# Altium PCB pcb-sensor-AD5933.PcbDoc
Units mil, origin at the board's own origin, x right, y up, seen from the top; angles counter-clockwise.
Board outline 2110 x 1945 mil, 2 copper layers (Top Layer, Bottom Layer); 28 components, 19 nets, 94 pads, 22 vias.
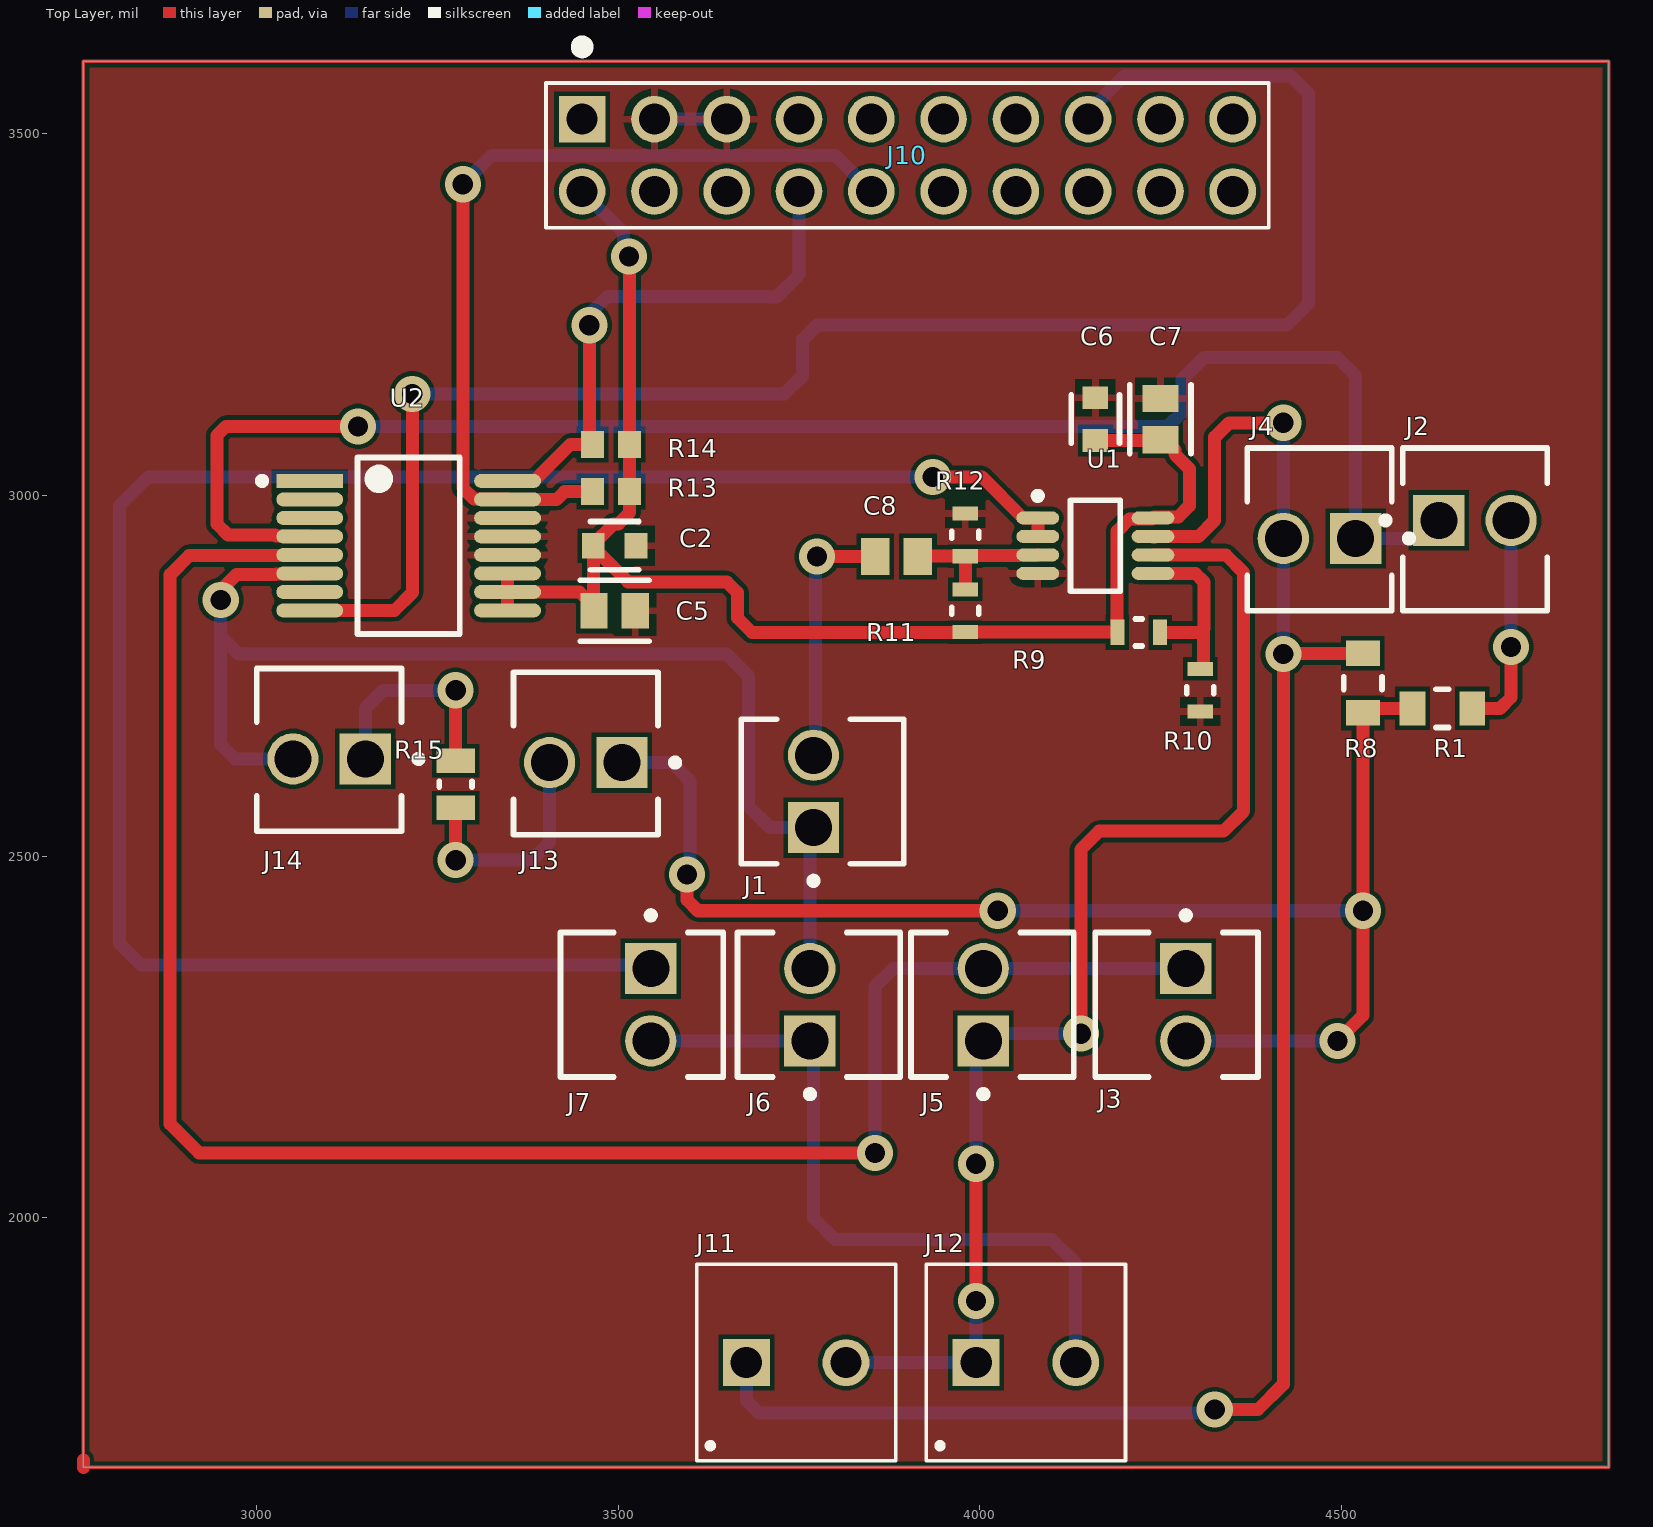
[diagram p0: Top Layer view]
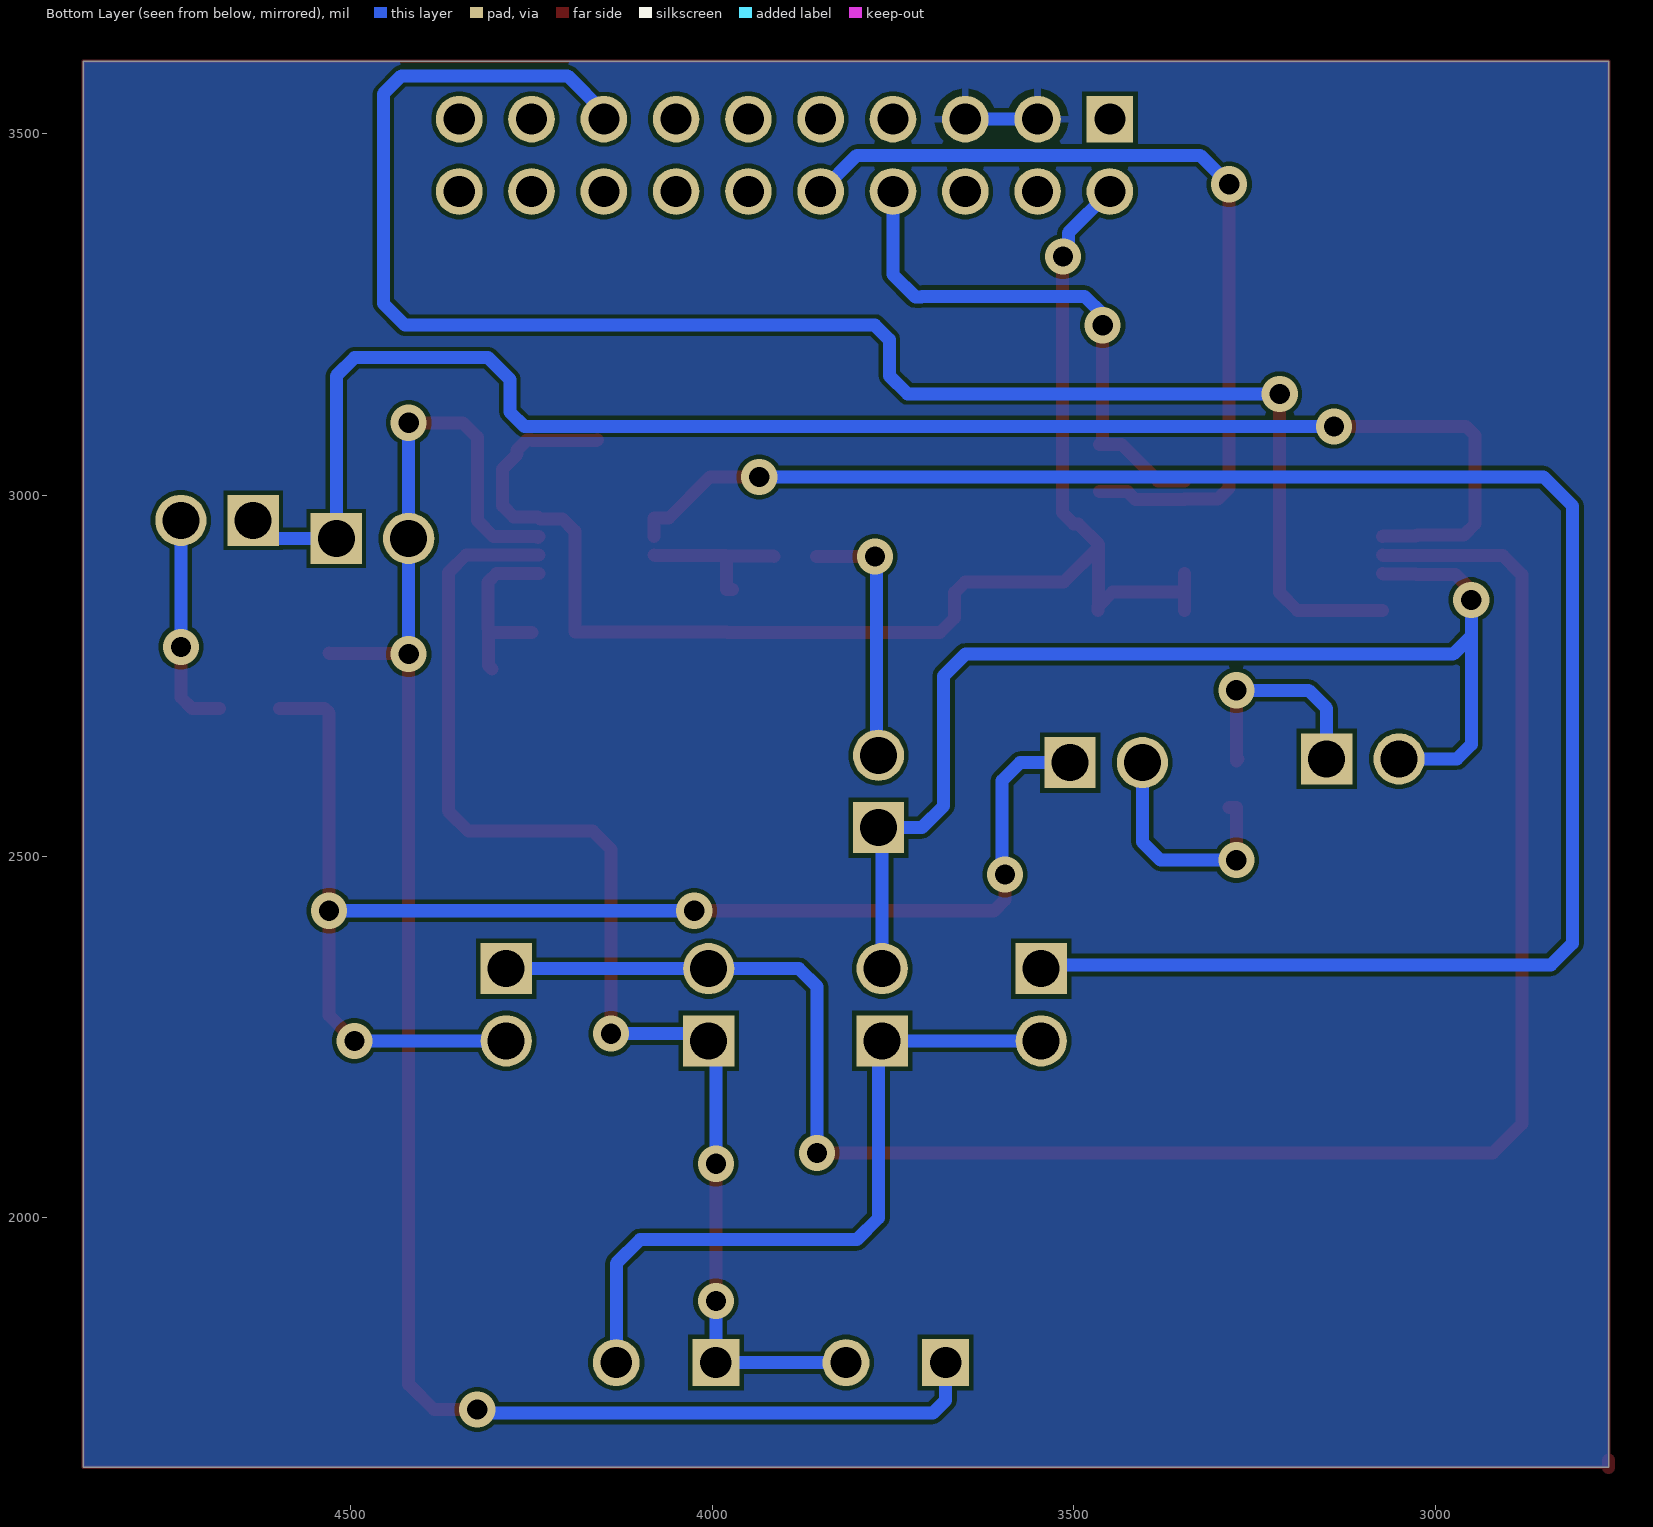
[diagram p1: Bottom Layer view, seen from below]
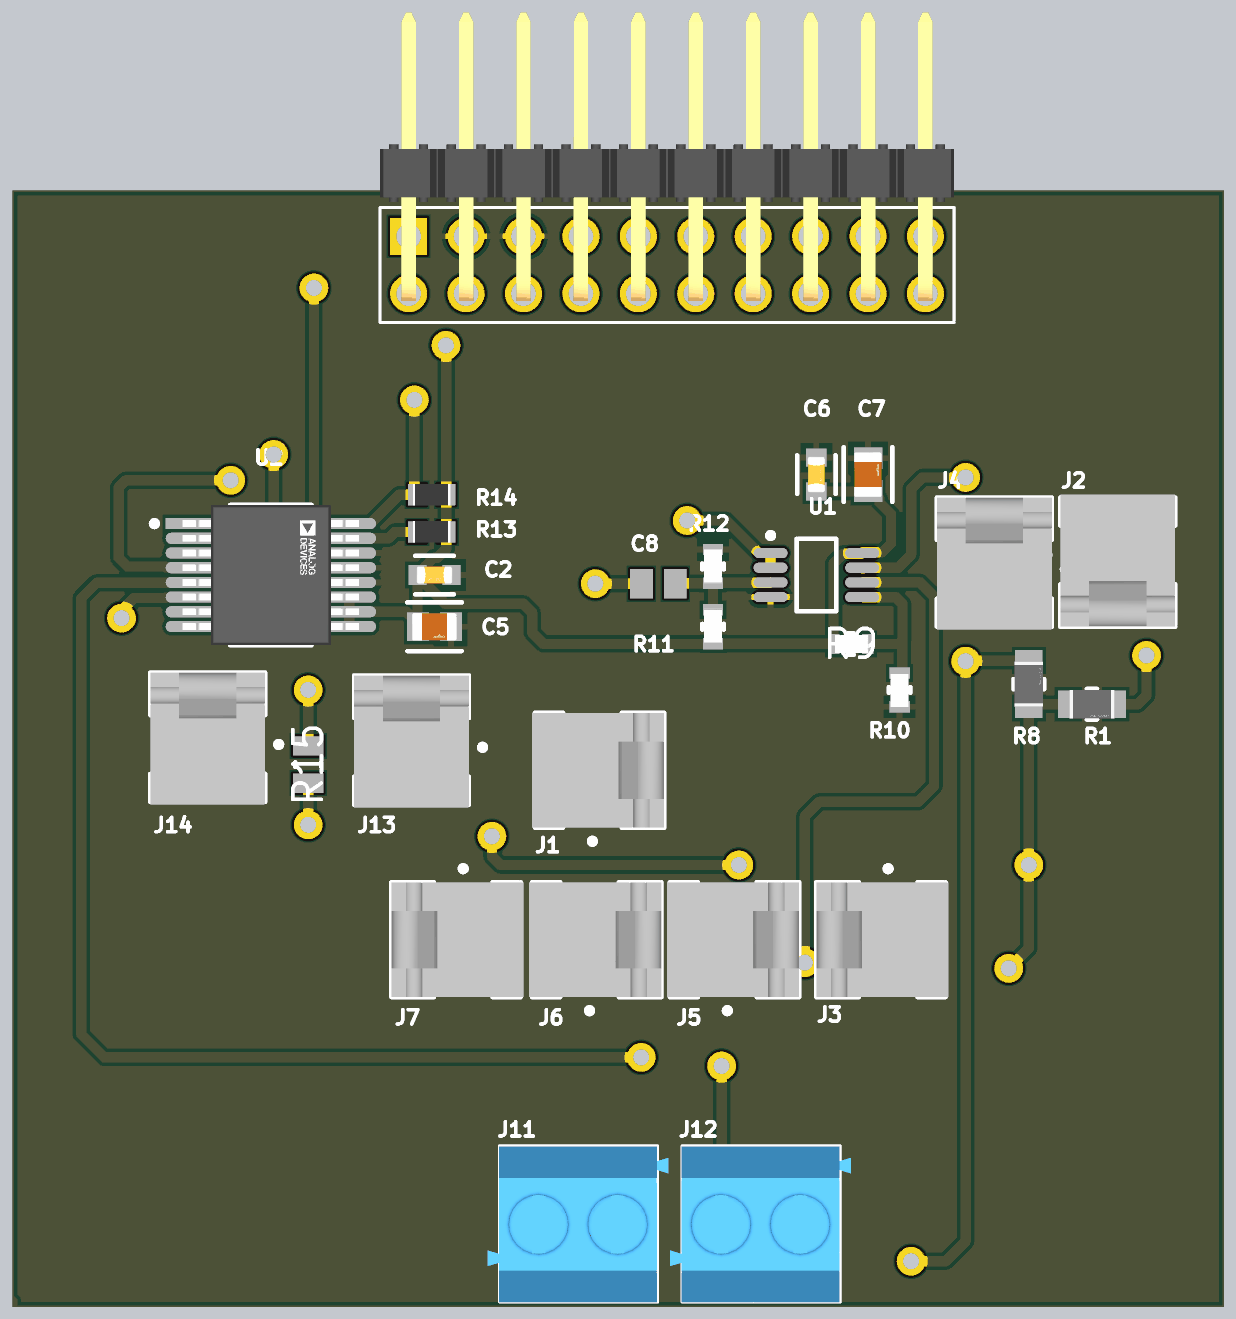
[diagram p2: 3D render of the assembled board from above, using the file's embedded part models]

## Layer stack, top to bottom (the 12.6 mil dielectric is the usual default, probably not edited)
Top Solder: solder mask 0.4, Solder Resist, Dk 3.5
Top Layer: signal copper 1.4
Dielectric 1: dielectric 12.6, FR-4, Dk 4.8
Bottom Layer: signal copper 1.4
Bottom Solder: solder mask 0.4, Solder Resist, Dk 3.5

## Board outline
2760,1655 4870,1655 4870,3600 2760,3600

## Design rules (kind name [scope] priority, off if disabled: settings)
Clearance [All] p1: gap=6 ignorepadtopadclearanceinfootprint=FALSE except(0: Arc-Hole Track-Hole SMDPad-Hole THPad-Hole Via-Hole Fill-Hole Poly-Hole Region-Hole Text-Hole)
PolygonConnect [All] p1: connectstyle=Relief reliefconductorwidth=10 reliefentries=4 polygonreliefangle="90 Angle" airgapwidth=10
RoutingVias [All] p1: holewidth=28 width=50 viastyle="Through Hole" minholewidth=28 minwidth=50 maxholewidth=28 maxwidth=50
SolderMaskExpansion [All] p1: expansion=4 istentingtop=FALSE
Width [All] p1: maxlimit=10 minlimit=10 preferedwidth=10
30 further rules are at their usual default settings.

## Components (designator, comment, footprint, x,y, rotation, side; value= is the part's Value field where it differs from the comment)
C2 "CC0603KRX7R8BB104" FP-CC0603-DA-MFG 3495,2930 r0 top value="100 nF"
C5 "GRM21BR61C106KE15L" FP-GRM21B-0_1-IPC_C 3495,2840 r0 top
C6 "CC0603KRX7R8BB104" FP-CC0603-DA-MFG 4160,3105 r90 top value="100 nF"
C7 "GRM21BR61C106KE15L" FP-GRM21B-0_1-IPC_C 4250,3105 r90 top
C8 "GRM219R61A475KE34D" CAPC2013X95X45LL10T25 3885,2915 r0 top
J1 "" TECO-640456-2_V 3770,2590 r270 top
J2 "" TECO-640456-2_V 4685,2965 r180 top
J3 "" TECO-640456-2_V 4285,2295 r90 top
J4 "" TECO-640456-2_V 4470,2940 r0 top
J5 "" TECO-640456-2_V 4005,2295 r270 top
J6 "" TECO-640456-2_V 3765,2295 r270 top
J7 "" TECO-640456-2_V 3545,2295 r90 top
J10 "10129382-920002BLF" "Base Board Modular Connector (MALE)" 3900,3470 r180 top
J11 "" "Terminal Block 2-position" 3677.2,1800 r0 top
J12 "TB0011-350-02BE" "Terminal Block 2-position" 3995,1800 r0 top
J13 "" TECO-640456-2_V 3455,2630 r0 top
J14 "" TECO-640456-2_V 3100,2635 r0 top
R1 "AC0805FR-07107RL" FP-AC0805-MFG 4640,2705 r0 top value=107Ω
R8 "AC0805FR-07107RL" FP-AC0805-MFG 4530,2740 r90 top value=107Ω
R9 "" FP-TNPU0603-e3-MFG 4220,2810 r180 top
R10 "" FP-TNPU0603-e3-MFG 4305,2730 r90 top
R11 "" FP-TNPU0603-e3-MFG 3980,2840 r270 top
R12 "" FP-TNPU0603-e3-MFG 3980,2945 r270 top
R13 "CRCW060310K0FKEA" RESC1609X50X30NL8T20 3490,3005 r180 top
R14 "CRCW060310K0FKEA" RESC1609X50X30NL8T20 3490,3070 r0 top
R15 "CRCW08050000Z0EA" RESC2013X50X30LL20T20 3275,2600 r90 top
U1 "" ADI-RM-8_L 4160,2930 r0 top
U2 "AD5933WYRSZ-REEL7" FP-RS-16-IPC_A 3210,2930 r0 top

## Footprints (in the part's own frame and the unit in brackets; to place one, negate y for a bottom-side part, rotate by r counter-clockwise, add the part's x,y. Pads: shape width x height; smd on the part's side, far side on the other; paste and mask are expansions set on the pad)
ADI-RM-8_L [mm] "SOP, 8-Leads, Body 3x3mm, Pitch 0.65mm, IPC High Density"
  oval 1.5x0.45 smd: 1(-2.025,0.975) 2(-2.025,0.325) 3(-2.025,-0.325) 4(-2.025,-0.975) 5(2.025,-0.975) 6(2.025,-0.325) 7(2.025,0.325) 8(2.025,0.975)
  silkscreen extent -2.15,-1.6 0.87,1.87, body extent -1.6,-1.6 1.6,1.6, height 1.1
"Base Board Modular Connector (MALE)" [mil] "10129382-920002BLF"
  rect 64.5x64.5 hole 43 mask+4.02: 1(450,-50)
  round 64.5 hole 43 mask+4.02: 2(350,-50) 3(250,-50) 4(150,-50) 5(50,-50) 6(-50,-50) 7(-150,-50) 8(-250,-50) 9(-350,-50) 10(-450,-50) 11(450,50) 12(350,50) 13(250,50) 14(150,50) 15(50,50) 16(-50,50) 17(-150,50) 18(-250,50) 19(-350,50) 20(-450,50)
  silkscreen extent -500,-158 500,100, body extent -500,-440 500,62, height 190
CAPC2013X95X45LL10T25 [mm] "Chip Capacitor, 2-Leads, Body 2.00x1.25mm, IPC High Density"
  rect 1x1.3 smd: 1(-0.75,0) 2(0.75,0)
  body extent -1.05,-0.67 1.05,0.68, height 0.95
FP-AC0805-MFG [mm]
  rect 0.9x1.2 smd paste+0 mask+0: 1(-1.05,0) 2(1.05,0)
  silkscreen extent -0.23,-0.67 0.23,0.67, body extent -1.6,-0.77 1.6,0.77, height 0.25
FP-CC0603-DA-MFG [mm]
  rect 0.8x0.9 smd paste+0 mask+0: 1(-0.75,0) 2(0.75,0)
  silkscreen extent -0.85,-0.85 0.85,0.85, body extent -1.35,-0.75 1.35,0.75, height 0.25
FP-GRM21B-0_1-IPC_C [mil]
  rect 37.71x49.69 smd paste+0 mask+0: 1(-28.63,0) 2(28.63,0)
  silkscreen extent -47,-42 47,42, body extent -51,-31 51,31, height 10
FP-RS-16-IPC_A [mm]
  rect 2.353x0.495 smd paste+0 mask+0: 1(-3.475,2.275)
  rrect100% 2.353x0.495 smd paste+0 mask+0: 2(-3.475,1.625) 3(-3.475,0.975) 4(-3.475,0.325) 5(-3.475,-0.325) 6(-3.475,-0.975) 7(-3.475,-1.625) 8(-3.475,-2.275) 9(3.475,-2.275) 10(3.475,-1.625) 11(3.475,-0.975) 12(3.475,-0.325) 13(3.475,0.325) 14(3.475,0.975) 15(3.475,1.625) 16(3.475,2.275)
  silkscreen extent -5.28,-3.1 1.8,3.1, body extent -5.15,-3.6 5.15,3.6, height 0.25
FP-TNPU0603-e3-MFG [mm]
  rect 0.5x0.9 smd paste+0 mask+0: 1(-0.75,0) 2(0.75,0)
  silkscreen extent -0.13,-0.48 0.13,0.48, body extent -1.1,-0.58 1.1,0.58, height 0.25
RESC1609X50X30NL8T20 [mm] "Chip Resistor, 2-Leads, Body 1.65x0.95mm, IPC Medium Density"
  rect 0.8x0.95 smd: 1(-0.65,0) 2(0.65,0)
  body extent -0.82,-0.48 0.82,0.48, height 0.5
RESC2013X50X30LL20T20 [mm] "Chip Resistor, 2-Leads, Body 2.00x1.25mm, IPC High Density"
  rect 0.85x1.35 smd: 1(-0.825,0) 2(0.825,0)
  silkscreen extent -0.1,-0.58 0.1,0.58, body extent -1.1,-0.72 1.1,0.72, height 0.5
TECO-640456-2_V [mm] "HDR, 2-Leads, Body 5.715x5.08mm, Pitch 2.54mm"
  rect 1.8x1.8 hole 1.3: 1(1.27,0)
  round 1.8 hole 1.3: 2(-1.27,0)
  silkscreen extent -2.54,-2.54 3.26,3.18, body extent -2.54,-2.67 2.54,3.17, height 9.4
"Terminal Block 2-position" [mm]
  rect 1.65x1.65 hole 1.1 mask+0.102: 1(0,0)
  round 1.65 hole 1.1 mask+0.102: 2(3.5,0)
  silkscreen extent -1.75,-3.45 5.25,3.45, body extent -2.28,-3.47 5.72,3.43, height 8.5

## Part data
C2 C6: library part CMP-03422-000234-1, "CAP CER 0.1UF 25V X7R 0603", Capacitance="100 nF", Manufacturer=YAGEO, Package=CC0603-DA, Temperature="-55°C to +125°C", Temperature Characteristic=X7R, Temperature Coefficient=15%, Temperature Range High=+125°C, Temperature Range Low=-55°C, Tolerance=0.1, Voltage="25 V"
C5 C7: library part CMP-2007-03453-2, "Chip Multilayer Ceramic Capacitors for General Purpose, 0805, 10uF, X5R, 15%, 10%, 16V", Capacitance=10uF, Case Code (Imperial)=0805, Case Code (Metric)=2012, Dielectric=X5R, Max Operating Temperature=85°C, Min Operating Temperature=-55°C, Package Quantity=1, Tolerance=10%, Voltage=16V
C8: library part CMP-2007-00178-1, Manufacturer=Murata
J1 J2 J3 J4 J5 J6 J7 J13 J14: library part CMP-2000-05417-1, "Male Header, Pitch 2.54 mm, 1 x 2 Position, Height 10.49 mm, Tail Length 3.556 mm, -55 to 105 degC, RoHS, Bulk", Color=White, Current, Rating="5 /  / A", Flammability Rating=UL94V-0, Manufacturer="TE Connectivity", Temperature, Operating="-55to+105 /  / degC", Voltage, Rating="250 /  / V"
J10: library part "Base Board Modular Connector (MALE)"
J11: library part TB0011-350-02BE, "Fixed Terminal Blocks 2 Poles, Screw Type, Horizontal, 3.50 Pitch, 24-18 (AWG), Blue, Terminal Block Connector", Supplier Part Number 1=2223-TB0011-350-02BE-ND
J12: "Fixed Terminal Blocks 2 Poles, Screw Type, Horizontal, 3.50 Pitch, 24-18 (AWG), Blue, Terminal Block Connector", Supplier Part Number 1=2223-TB0011-350-02BE-ND
R1 R8: library part CMP-03412-037308-1, "Res SMD 107 Ohm 1% 1/8W 0805", Manufacturer=Yageo, Package=AC0805, Power Rating=1/8W, Resistance=107Ω, Temperature="-55°C to +155°C", Temperature Range High=+155°C, Temperature Range Low=-55°C, Tolerance=0.01, Voltage Rating=150V
R9 R10 R11 R12: library part CMP-02407-013067-1, "RES SMD 50K OHM 0.02% 1/10W 0603", Case Code (Imperial)=0603, Case Code (Metric)=1608, Max Operating Temperature=125°C, Max Power Dissipation=100mW, Min Operating Temperature=-55°C, Resistance=50kR, Resistor Type="Thin Film", Temperature Coefficient=5ppm/°C, Tolerance=0.02%
R13 R14: library part CMP-1666-00005-4, "Chip Resistor, 10 KOhm, +/- 1%, 100 mW, -55 to 155 degC, 0603 (1608 Metric), RoHS, Tape and Reel", Manufacturer="Vishay Semiconductor", Max Operating Temperature="155 degC", Min Operating Temperature="-55 degC", Package Quantity=5000, Voltage Rating="75 V"
R15: library part CMP-2001-04896-1, Manufacturer="Vishay Dale"
U1: library part CMP-0384-01320-2, "Double Channel Wide Bandwidth Operational Amplifier, 10 MHz BW, 5 V/us SR, Industrial, 8-pin SOIC (R-8), Reel", Amplifiers Per Package=2, Generic Part Number=AD8606, Input Bias Current=200fA, Input Offset Voltage=20uV, Manufacturer="Analog Devices", PartNumber=AD8606ARZ-REEL
U2: library part CMP-09111-000002-1, "12BIT 1 MSPS, IMPEDANCE CONVERTE", Frequency=16.776MHz, Nominal Supply Current=15mA

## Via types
v1: diameter 50, hole 28, Top Layer to Bottom Layer, 22 vias

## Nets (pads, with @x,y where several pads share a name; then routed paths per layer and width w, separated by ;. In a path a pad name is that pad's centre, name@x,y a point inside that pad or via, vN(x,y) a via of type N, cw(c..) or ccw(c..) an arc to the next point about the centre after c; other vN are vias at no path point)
3V3: C2.1 C5.1 C6.1 C7.1 J10.11 R9.2 R11.2 R13.1 R14.2 U1.8 U2.9 U2.10 U2.11 | length 2060.3
  Top Layer w18: U2.9 U2.10 ; U2.11 U2.10 ; C5.1 3466.37,2845.99 C5.1@3465.47,2846.89 ; v1@3515.59,3329.41 R13.1 3515.59,2975.59 3500.08,2960.08 3493.58,2960.08 3465.47,2931.97 C2.1 C2.1@3465.47,2928.03 ; C6.1@4159.1,3076.37 C6.1 4249.1,3075.47 C7.1 4255.99,3076.37 4269.85,3062.52 4269.85,3056.53 4290,3036.37 4290,2985 4274.86,2969.86 4241.2,2969.86 U1.8 4238.25,2966.91 4206.91,2966.91 4190,2950 4190,2810.47 R11.2 3979.53,2810 3685,2810 3665,2830 3665,2865 3650.15,2879.85 3513.66,2879.85 C2.1@3465.47,2928.03 ; U2.10 3446.34,2866.02 C5.1@3465.47,2846.89 ; C5.1@3465.47,2846.89 C2.1@3465.47,2928.03
  Bottom Layer w18: J10.11 3507.35,3362.65 3507.35,3337.65 v1(3515,3330)
GND: C2.2 C5.2 C6.2 C7.2 J10.2 J10.3 R10.1 R12.1 U1.4 U2.12 U2.13 U2.14 | length 100
  Bottom Layer w18: J10.2 J10.3
NetC8_1: C8.1 J1.2 | length 357.5
  Top Layer w18: v1(3775,2915) C8.1
  Bottom Layer w18: J1.2 3772.5,2642.5 3772.5,2912.5 v1(3775,2915)
NetC8_2: C8.2 R11.1 R12.2 U1.3 | length 220.5
  Top Layer w18: C8.2 3915,2915.47 R12.2 ; R11.1@3972.13,2869.53 R11.1 R12.2 ; U1.3 4079.41,2916.34 3980.87,2916.34 R12.2
NetJ1_1: J1.1 J6.2 J14.2 U2.6 | length 1695.8
  Top Layer w18: v1@2950,2860 2950.86,2860.86 2950.86,2869.14 2971.72,2890 3025.6,2890 3026.36,2890.77 3072.34,2890.77 U2.6 ; J1.1@3760,2530 3765,2535 J1.1
  Bottom Layer w18: v1(2950,2855) 2950,2805 ; J14.2 2970,2635 2950,2655 2950,2805 ; J6.2 3765,2535 J1.1 3710,2540 3680,2570 3680,2750 3650,2780 2975,2780 2950,2805
NetJ2_1: J2.1 J4.1 U2.4 | length 2299.8
  Top Layer w18: U2.4 3072.34,2943.64 3026.36,2943.64 3025,2945 2960,2945 2945,2960 2945,3082.6 2957.4,3095 v1(3140,3095) ; J2.1@4610,2940 J2.1
  Bottom Layer w18: v1(3140,3095) 4260,3095 4280,3115 4280,3160 4310,3190 4495,3190 4520,3165 J4.1 4610,2940 J2.1
NetJ2_2: J2.2 R1.2 | length 304.9
  Top Layer w18: R1.2 4720,2705 4735,2720 v1(4735,2790)
  Bottom Layer w18: v1(4735,2790) J2.2
NetJ3_1: J3.1 J5.2 U2.5 | length 2626.4
  Top Layer w18: U2.5 3072.34,2916.36 2906.36,2916.36 2880,2890 2880,2130 2920,2090 v1(3855,2090)
  Bottom Layer w18: v1(3855,2090) 3855,2320 3880,2345 J5.2 J3.1
NetJ3_2: J3.2 J13.1 R1.1 R8.1 | length 1961.9
  Top Layer w18: v1(3595,2475) 3595,2440 3610,2425 v1(4025,2425) ; v1(4495,2245) 4530,2280 v1(4530,2425) R8.1 4536.34,2705 R1.1
  Bottom Layer w18: J13.1 3574.14,2630 3599.14,2605 3599.14,2479.14 v1(3595,2475) ; v1(4025,2425) v1(4530,2425) ; J3.2 v1(4495,2245)
NetJ4_2: J4.2 J11.1 R8.2 U1.7 | length 2579.3
  Top Layer w18: J11.1@3675,1797.8 J11.1 ; U1.7@4241.12,2941.4 U1.7 4302.8,2942.8 4325,2965 4325,3080 4345,3100 v1(4420,3100) ; v1(4325,1735) 4385,1735 4420,1770 v1(4420,2780) 4420.67,2780.67 4529.33,2780.67 R8.2 ; J4.2@4418.6,2941.4 J4.2
  Bottom Layer w18: J11.1 3677.2,1747.8 3695,1730 4320,1730 v1(4325,1735) ; v1(4420,2780) J4.2 v1(4420,3100)
NetJ5_1: J5.1 J11.2 J12.1 U1.6 | length 1751.8
  Top Layer w18: J12.1 J12.1@4005,1810 ; v1(3995,1885) v1(3995,2075) ; J5.1 J5.1@4010,2240 ; v1@4140,2260 4140,2510 4165,2535 4337.21,2535 4365,2562.79 4365,2892.79 4340.58,2917.2 U1.6
  Bottom Layer w18: J11.2 J12.1 v1(3995,1885) ; v1(3995,2075) 3995,2235 J5.1 4015,2255 v1(4140,2255)
NetJ6_1: J6.1 J7.2 J12.2 | length 993.1
  Bottom Layer w18: J7.2 J6.1 3770,2240 3770,2000 3800,1970 4100,1970 4132.8,1937.2 J12.2
NetJ7_1: J7.1 U1.1 U1.2 | length 2690.4
  Top Layer w18: v1(3935,3025) 4003.28,3025 4059.89,2968.39 U1.1 U1.2
  Bottom Layer w18: J7.1 3540,2350 2840,2350 2810,2380 2810,2460 2810,2985 2850,3025 v1(3935,3025)
NetJ10_8: J10.8 U2.8 | length 2397.1
  Top Layer w18: U2.8 3190.43,2840.43 3215,2865 v1(3215,3140) ; J10.8@4140.86,3529.14 J10.8
  Bottom Layer w18: v1(3215,3140) 3730,3140 3755,3165 3755,3215 3775,3235 4425,3235 4455,3265 4455,3555 4430,3580 4200,3580 4150,3530 J10.8
NetJ10_14: J10.14 R14.1 U2.16 | length 733.8
  Top Layer w18: U2.16 3383.23,3019.57 3433.66,3070 R14.1 3460,3074.41 v1(3460,3235)
  Bottom Layer w18: v1@3460,3250 3485,3275 3710,3275 3710.86,3274.14 3719.14,3274.14 3750,3305 J10.14
NetJ10_15: J10.15 R13.2 U2.15 | length 1213
  Top Layer w18: v1(3285,3430) 3285,3009.82 3300.56,2994.26 3346.53,2994.26 U2.15 3414.78,2993.98 3425.8,3005 R13.2
  Bottom Layer w18: v1(3285,3430) 3325,3470 3800,3470 J10.15
NetJ13_2: J13.2 R15.1 | length 332.7
  Top Layer w18: v1(3275,2495) R15.1 R15.1@3284.84,2567.52
  Bottom Layer w18: v1(3275,2495) 3380,2495 3405,2520 J13.2
NetJ14_1: J14.1 R15.2 | length 306.4
  Top Layer w18: R15.2@3272.48,2635 R15.2 v1(3275,2730)
  Bottom Layer w18: J14.1 3150,2705 3175,2730 v1(3275,2730)
NetR9_1: R9.1 R10.2 U1.5 | length 259.7
  Top Layer w18: U1.5 4298.39,2891.61 4310,2880 4310,2815.47 4309.53,2815 ; R9.1 4304.53,2810 4309.53,2815 ; R10.2 4309.53,2764.06 4309.53,2815
pads on no net: J10.1 J10.4 J10.5 J10.6 J10.7 J10.9 J10.10 J10.12 J10.13 J10.16 J10.17 J10.18 J10.19 J10.20 U2.1 U2.2 U2.3 U2.7
copper on no net: | length 8110
  Top Layer w5: 2760,1655 4870,1655 4870,3600 2760,3600 2760,1665
  Top Layer w18: 2760,1655 2760,1665

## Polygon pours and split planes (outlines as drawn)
GND on Top Layer "GND_L01_P001" (solid, pour order 1): 2760,3600 4870,3600 4870,1655 2760,1655
GND on Bottom Layer "GND_L02_P000" (solid, pour order 0): 2760,3600 4870,3600 4870,1655 2760,1655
